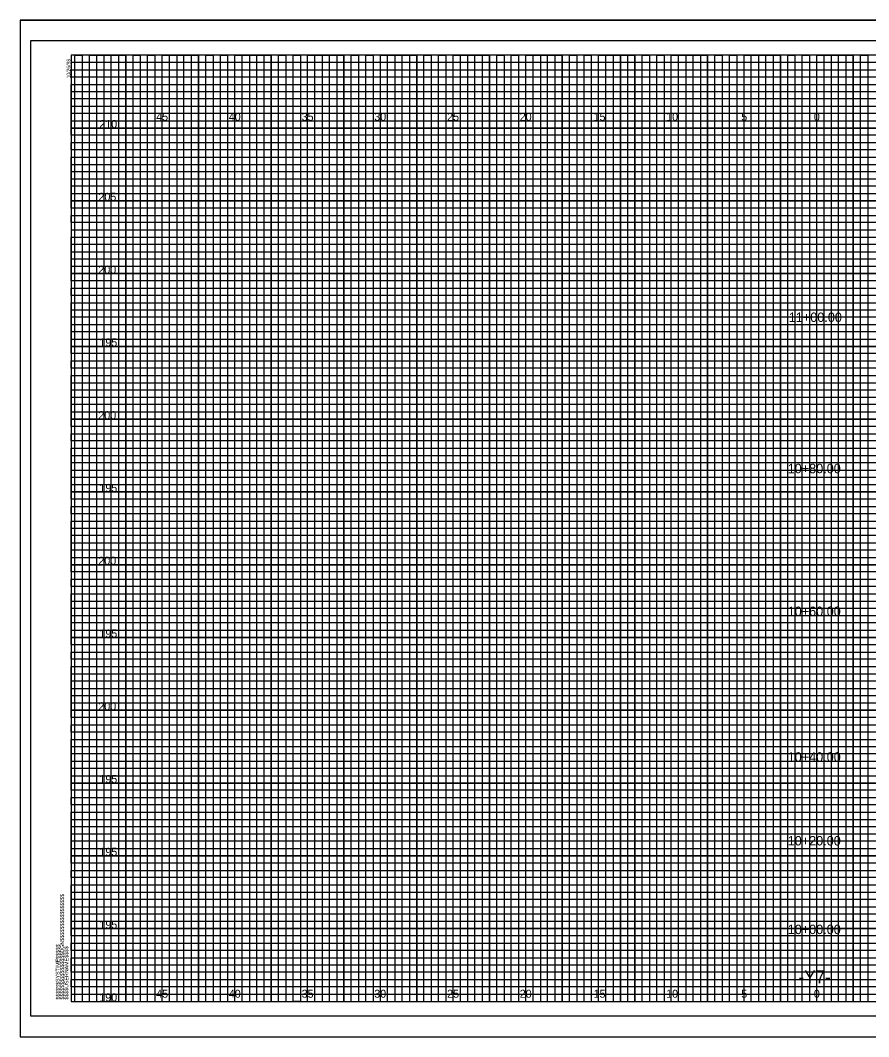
# Model space of a CAD drawing. Extents: x -4 to 103, y -2 to 351.
# Drawn here: x -3.5 to 54.8, y -2.4 to 67.4 of the extents above; entities that cross this region are included whole.
import ezdxf

# ---------------------------------------------------------------- set-up
doc = ezdxf.new("R2010")
doc.units = 0
for name, color, linetype in [('Exist XS Ground Line', 7, 'Continuous'), ('Old_Level_10', 7, 'Continuous'), ('Old_Level_16', 7, 'Continuous'), ('Old_Level_3', 7, 'Continuous'), ('Old_Level_4', 7, 'Continuous'), ('Old_Level_5', 7, 'Continuous'), ('Old_Level_6', 7, 'Continuous'), ('Old_Level_8', 7, 'Continuous'), ('Prop XS Finish Grade', 7, 'Continuous'), ('Prop XS SE Text', 7, 'Continuous'), ('Prop XS Subgrade Earthwork', 7, 'Continuous')]:
    doc.layers.add(name, color=color, linetype=linetype)

msp = doc.modelspace()

# ---------------------------------------------------------------- linework, layer by layer
at = {"layer": 'Old_Level_10'}
for p, q in [((1.25, 0), (1.25, 65)), ((3.75, 0), (3.75, 65)), ((6.25, 0), (6.25, 65)), ((8.75, 0), (8.75, 65)), ((11.25, 0), (11.25, 65)), ((13.75, 0), (13.75, 65)), ((16.25, 0), (16.25, 65)), ((18.75, 0), (18.75, 65)), ((21.25, 0), (21.25, 65)), ((23.75, 0), (23.75, 65)), ((26.25, 0), (26.25, 65)), ((28.75, 0), (28.75, 65)), ((31.25, 0), (31.25, 65)), ((33.75, 0), (33.75, 65)), ((36.25, 0), (36.25, 65)), ((38.75, 0), (38.75, 65)), ((41.25, 0), (41.25, 65)), ((43.75, 0), (43.75, 65)), ((46.25, 0), (46.25, 65)), ((48.75, 0), (48.75, 65)), ((51.25, 0), (51.25, 65)), ((53.75, 0), (53.75, 65)), ((0, 62.5), (74.25, 62.5)), ((0, 60), (102.5, 60)), ((0, 57.5), (102.5, 57.5)), ((0, 55), (102.5, 55)), ((0, 52.5), (102.5, 52.5)), ((0, 50), (102.5, 50)), ((0, 47.5), (102.5, 47.5)), ((0, 45), (102.5, 45)), ((0, 42.5), (102.5, 42.5)), ((0, 40), (102.5, 40)), ((0, 37.5), (102.5, 37.5)), ((0, 35), (102.5, 35)), ((0, 32.5), (102.5, 32.5)), ((0, 30), (102.5, 30)), ((0, 27.5), (102.5, 27.5)), ((0, 25), (102.5, 25)), ((0, 22.5), (102.5, 22.5)), ((0, 20), (102.5, 20)), ((0, 17.5), (102.5, 17.5)), ((0, 15), (102.5, 15)), ((0, 12.5), (102.5, 12.5)), ((0, 10), (102.5, 10)), ((0, 7.5), (102.5, 7.5)), ((0, 5), (102.5, 5)), ((0, 2.5), (102.5, 2.5))]:
    msp.add_line(p, q, dxfattribs=at)
at = {"layer": 'Old_Level_3'}
for p, q in [((-3.5, 67.4), (103.4, 67.4)), ((-3.5, 67.4), (-3.5, -2.425)), ((-3.5, -2.425), (102.1625, -2.425))]:
    msp.add_line(p, q, dxfattribs=at)
at = {"layer": 'Old_Level_4'}
for points in [[(0.25, 0), (0.25, 65), (0.75, 65), (0.75, 0), (1.75, 0), (1.75, 65), (2.25, 65), (2.25, 0), (2.75, 0), (2.75, 65), (3.25, 65), (3.25, 0), (4.25, 0), (4.25, 65), (4.75, 65), (4.75, 0), (5.25, 0), (5.25, 65), (5.75, 65), (5.75, 0), (6.75, 0), (6.75, 65), (7.25, 65), (7.25, 0), (7.75, 0), (7.75, 65), (8.25, 65), (8.25, 0), (9.25, 0), (9.25, 65), (9.75, 65), (9.75, 0), (10.25, 0), (10.25, 65), (10.75, 65), (10.75, 0), (11.75, 0), (11.75, 65), (12.25, 65), (12.25, 0), (12.75, 0), (12.75, 65), (13.25, 65), (13.25, 0), (14.25, 0), (14.25, 65), (14.75, 65), (14.75, 0), (15.75, 0), (15.25, 0), (15.25, 65), (15.75, 65), (15.75, 0), (16.75, 0), (16.75, 65), (17.25, 65), (17.25, 0), (17.75, 0), (17.75, 65), (18.25, 65), (18.25, 0), (19.25, 0), (19.25, 65), (19.75, 65), (19.75, 0), (20.25, 0), (20.25, 65), (20.75, 65), (20.75, 0), (21.75, 0), (21.75, 65), (22.25, 65), (22.25, 0), (22.75, 0), (22.75, 65), (23.25, 65), (23.25, 0), (24.25, 0), (24.25, 65), (24.75, 65), (24.75, 0), (25.25, 0), (25.25, 65), (25.75, 65), (25.75, 0), (26.75, 0), (26.75, 65), (27.25, 65), (27.25, 0), (27.75, 0), (27.75, 65), (28.25, 65), (28.25, 0), (29.25, 0), (29.25, 65), (29.75, 65), (29.75, 0), (30.25, 0), (30.25, 65), (30.75, 65), (30.75, 0)], [(30.75, 0), (31.75, 0), (31.75, 65), (32.25, 65), (32.25, 0), (32.75, 0), (32.75, 65), (33.25, 65), (33.25, 0), (34.25, 0), (34.25, 65), (34.75, 65), (34.75, 0), (35.25, 0), (35.25, 65), (35.75, 65), (35.75, 0), (36.75, 0), (36.75, 65), (37.25, 65), (37.25, 0), (37.75, 0), (37.75, 65), (37.75, 0)], [(38.25, 65), (38.25, 0), (39.25, 0), (39.25, 65), (39.75, 65), (39.75, 0), (40.25, 0), (40.25, 65), (40.75, 65), (40.75, 0), (41.75, 0), (41.75, 65), (42.25, 65), (42.25, 0), (42.75, 0), (42.75, 65), (43.25, 65), (43.25, 0), (43.75, 0), (44.25, 0), (44.25, 65), (44.75, 65), (44.75, 0), (45.25, 0), (45.25, 65), (45.75, 65), (45.75, 0), (46.75, 0), (46.75, 65), (47.25, 65), (47.25, 0), (47.75, 0), (47.75, 65), (48.25, 65), (48.25, 0), (49.25, 0), (49.25, 65), (49.75, 65), (49.75, 0), (50.25, 0), (50.25, 65), (50.75, 65), (50.75, 0), (51.75, 0), (51.75, 65), (52.25, 65), (52.25, 0), (52.75, 0), (52.75, 65), (53.25, 65), (53.25, 0), (54.25, 0), (54.25, 65), (54.75, 65), (54.75, 0), (55.25, 0)], [(0, 62), (0, 63), (74.25, 63), (74.25, 63.5), (0, 63.5), (0, 64), (74.25, 64), (74.25, 64.5), (0, 64.5)], [(102.5, 62), (0, 62)], [(102.5, 61), (0, 61), (0, 61.5), (102.5, 61.5)], [(102.5, 59.5), (0, 59.5), (0, 60.5), (102.5, 60.5)], [(102.5, 58.5), (0, 58.5), (0, 59), (102.5, 59)], [(102.5, 57), (0, 57), (0, 58), (102.5, 58)], [(102.5, 56), (0, 56), (0, 56.5), (102.5, 56.5)], [(102.5, 54.5), (0, 54.5), (0, 55.5), (102.5, 55.5)], [(102.5, 53.5), (0, 53.5), (0, 54), (102.5, 54)], [(0, 53), (102.5, 53)], [(102.5, 52), (0, 52)], [(102.5, 51), (0, 51), (0, 51.5), (102.5, 51.5)], [(102.5, 49.5), (0, 49.5), (0, 50.5), (102.5, 50.5)], [(102.5, 48.5), (0, 48.5), (0, 49), (102.5, 49)], [(102.5, 47), (0, 47), (0, 48), (102.5, 48)], [(102.5, 46), (0, 46), (0, 46.5), (102.5, 46.5)], [(102.5, 44.5), (0, 44.5), (0, 45.5), (102.5, 45.5)], [(102.5, 43.5), (0, 43.5), (0, 44), (102.5, 44)], [(102.5, 42), (0, 42), (0, 43), (102.5, 43)], [(102.5, 41), (0, 41), (0, 41.5), (102.5, 41.5)], [(102.5, 39.5), (0, 39.5), (0, 40.5), (102.5, 40.5)], [(102.5, 38.5), (0, 38.5), (0, 39), (102.5, 39)], [(102.5, 37), (0, 37), (0, 38), (102.5, 38)], [(102.5, 36), (0, 36), (0, 36.5), (102.5, 36.5)], [(102.5, 34.5), (0, 34.5), (0, 35.5), (102.5, 35.5)], [(102.5, 33.5), (0, 33.5), (0, 34), (102.5, 34)], [(102.5, 32), (0, 32), (0, 33), (102.5, 33)], [(102.5, 31), (0, 31), (0, 31.5)], [(0, 31.5), (102.5, 31.5)], [(102.5, 29.5), (0, 29.5), (0, 30.5), (102.5, 30.5)], [(102.5, 28.5), (0, 28.5), (0, 29), (102.5, 29)], [(102.5, 27), (0, 27), (0, 28), (102.5, 28)], [(102.5, 26), (0, 26), (0, 26.5), (102.5, 26.5)], [(102.5, 24.5), (0, 24.5), (0, 25.5), (102.5, 25.5)], [(102.5, 23.5), (0, 23.5), (0, 24), (102.5, 24)], [(102.5, 22), (0, 22), (0, 23), (102.5, 23)], [(102.5, 21), (0, 21), (0, 21.5), (102.5, 21.5)], [(102.5, 19.5), (0, 19.5), (0, 20.5), (102.5, 20.5)], [(102.5, 18.5), (0, 18.5), (0, 19), (102.5, 19)], [(102.5, 17), (0, 17), (0, 18), (102.5, 18)], [(102.5, 16), (0, 16), (0, 16.5), (102.5, 16.5)], [(102.5, 14.5), (0, 14.5), (0, 15.5), (102.5, 15.5)], [(102.5, 13.5), (0, 13.5), (0, 14), (102.5, 14)], [(102.5, 12), (0, 12), (0, 13), (102.5, 13)], [(102.5, 11), (0, 11), (0, 11.5), (102.5, 11.5)], [(102.5, 9.5), (0, 9.5), (0, 10.5), (102.5, 10.5)], [(102.5, 8.5), (0, 8.5), (0, 9), (102.5, 9)], [(102.5, 7), (0, 7), (0, 8), (102.5, 8)], [(102.5, 6), (0, 6), (0, 6.5), (102.5, 6.5)], [(102.5, 4.5), (0, 4.5), (0, 5.5), (102.5, 5.5)], [(102.5, 3.5), (0, 3.5), (0, 4), (102.5, 4)], [(102.5, 2), (0, 2), (0, 3), (102.5, 3)], [(102.5, 1), (0, 1), (0, 1.5), (102.5, 1.5)], [(0, 0.5), (102.5, 0.5)]]:
    msp.add_lwpolyline(points, dxfattribs=at)
at = {"layer": 'Old_Level_5'}
msp.add_lwpolyline([(103.4, 67.4), (-3.5, 67.4), (-3.5, -2.425), (103.4, -2.425)], close=True, dxfattribs=at)
at = {"layer": 'Old_Level_6'}
for p, q in [((0, 0), (0, 0)), ((0, 0), (0, 0)), ((-3.5, -2.425), (103.4, -2.425))]:
    msp.add_line(p, q, dxfattribs=at)
msp.add_lwpolyline([(102.5, 65), (0, 65), (0, 0), (102.5, 0)], close=True, dxfattribs=at)
at = {"layer": 'Old_Level_8'}
for points in [[(1.25, 0), (1.25, 65), (3.75, 65), (3.75, 0), (6.25, 0), (6.25, 65), (8.75, 65), (8.75, 0), (11.25, 0), (11.25, 65), (13.75, 65), (13.75, 0), (16.25, 0), (16.25, 65), (18.75, 65), (18.75, 0), (21.25, 0), (21.25, 65), (23.75, 65), (23.75, 0), (26.25, 0), (26.25, 65), (28.75, 65), (28.75, 0), (31.25, 0), (31.25, 65), (33.75, 65), (33.75, 0), (36.25, 0), (36.25, 65), (38.75, 65), (38.75, 0), (41.25, 0), (41.25, 65), (43.75, 65), (43.75, 0), (46.25, 0), (46.25, 65), (48.75, 65), (48.75, 0), (51.25, 0), (51.25, 65), (53.75, 65), (53.75, 0)], [(102.5, 60), (0, 60), (0, 62.5), (74.25, 62.5)], [(102.5, 55), (0, 55), (0, 57.5), (102.5, 57.5)], [(102.5, 50), (0, 50), (0, 52.5), (102.5, 52.5)], [(102.5, 45), (0, 45), (0, 47.5), (102.5, 47.5)], [(102.5, 40), (0, 40), (0, 42.5), (102.5, 42.5)], [(102.5, 35), (0, 35), (0, 37.5), (102.5, 37.5)], [(102.5, 30), (0, 30), (0, 32.5), (102.5, 32.5)], [(102.5, 25), (0, 25), (0, 27.5), (102.5, 27.5)], [(102.5, 20), (0, 20), (0, 22.5), (102.5, 22.5)], [(102.5, 15), (0, 15), (0, 17.5), (102.5, 17.5)], [(102.5, 10), (0, 10), (0, 12.5), (102.5, 12.5)], [(102.5, 5), (0, 5), (0, 7.5), (102.5, 7.5)], [(0, 2.5), (102.5, 2.5)]]:
    msp.add_lwpolyline(points, dxfattribs=at)
at = {"layer": 'Prop XS SE Text'}
msp.add_lwpolyline([(103, 66), (-2.8, 66), (-2.8, -1), (103, -1)], close=True, dxfattribs=at)

# ---------------------------------------------------------------- texts
at = {"layer": 'Exist XS Ground Line'}
msp.add_text('-Y7-', height=0.875, dxfattribs=at).set_placement((49.9985, 1.25))
at = {"layer": 'Old_Level_16'}
for s, p in [('45', (5.8399, 60.5)), ('40', (10.8313, 60.5)), ('35', (15.8399, 60.5)), ('30', (20.8313, 60.5)), ('25', (25.8399, 60.5)), ('20', (30.8313, 60.5)), ('15', (35.9058, 60.5)), ('10', (40.8971, 60.5)), ('5', (46.0574, 60.5)), ('0', (51.0488, 60.5)), ('0', (51.0488, 60.5)), ('45', (5.8399, 0.25)), ('40', (10.8313, 0.25)), ('35', (15.8399, 0.25)), ('30', (20.8313, 0.25)), ('25', (25.8399, 0.25)), ('20', (30.8313, 0.25)), ('15', (35.9058, 0.25)), ('10', (40.8971, 0.25)), ('5', (46.0574, 0.25)), ('0', (51.0488, 0.25)), ('0', (51.0488, 0.25))]:
    msp.add_text(s, height=0.55, dxfattribs=at).set_placement(p)
at = {"layer": 'Old_Level_6'}
for s, height, p in [('10/26/98', 0.25, (-0.0625, 63.4095)), ('$$$$$$$$$$$$$$$$DGN$$$$$$$$$$$$$$$$', 0.2625, (-0.5, 0.125)), ('$$$$$$SYSTIME$$$$$', 0.2625, (-0.7973, 0.1247)), ('$$$$USERNAME$$$$', 0.2625, (-0.2, 0.125))]:
    msp.add_text(s, height=height, rotation=90, dxfattribs=at).set_placement(p)
at = {"layer": 'Old_Level_8'}
msp.add_text('040397', height=0.0025, rotation=90, dxfattribs=at).set_placement((-0.0007, 64.9864))
at = {"layer": 'Prop XS Finish Grade'}
for s, p in [('210', (1.9296, 60)), ('205', (1.8724, 55)), ('200', (1.8638, 50)), ('195', (1.9383, 45)), ('200', (1.8638, 40)), ('195', (1.9383, 35)), ('200', (1.8638, 30)), ('195', (1.9383, 25)), ('200', (1.8638, 20)), ('195', (1.9383, 15)), ('195', (1.9383, 10)), ('195', (1.9383, 5)), ('190', (1.9296, 0))]:
    msp.add_text(s, height=0.55, dxfattribs=at).set_placement(p)
at = {"layer": 'Prop XS Subgrade Earthwork'}
for s, p in [('11+00.00', (49.3286, 46.6773)), ('10+80.00', (49.2508, 36.2854)), ('10+60.00', (49.2508, 26.4737)), ('10+40.00', (49.2508, 16.466)), ('10+20.00', (49.2508, 10.7102)), ('10+00.00', (49.2508, 4.6218))]:
    msp.add_text(s, height=0.65, dxfattribs=at).set_placement(p)

doc.saveas('drawing.dxf')
